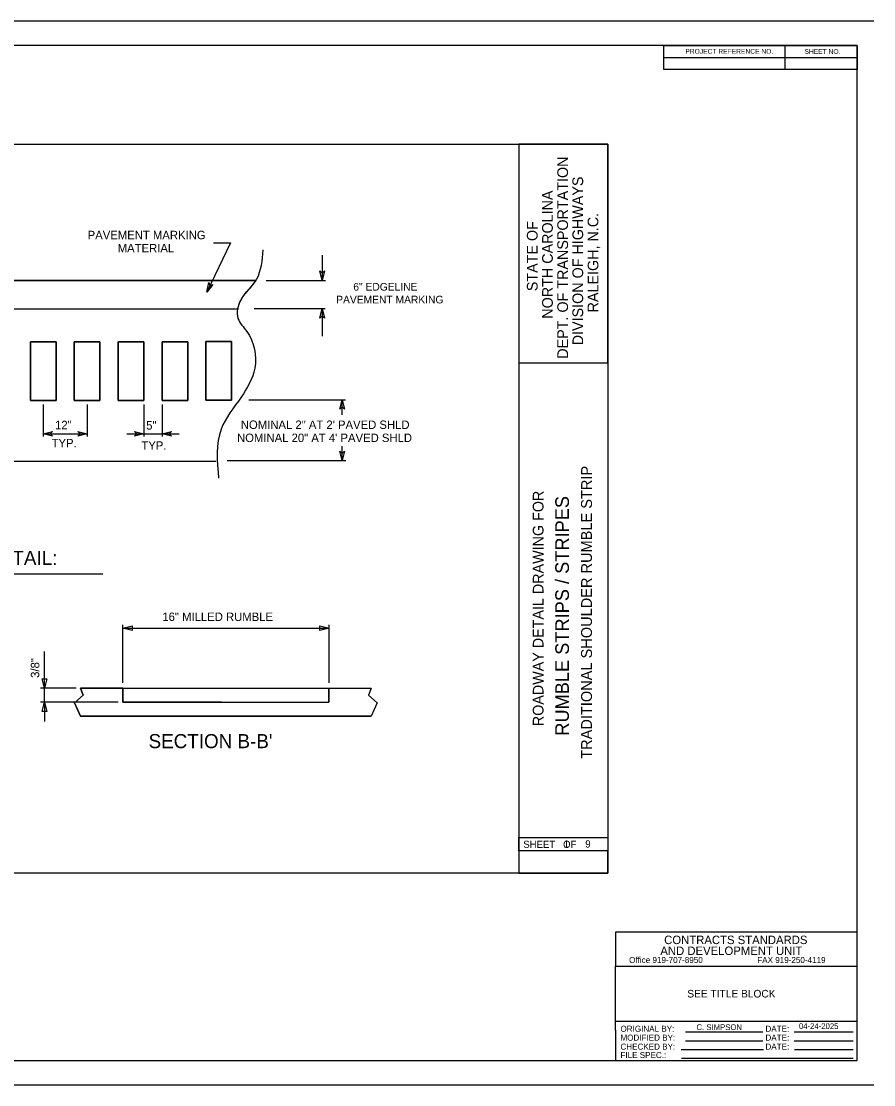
# Model space of a CAD drawing. Extents: x 1994737 to 2001433, y 527447 to 529360.
# Drawn here: x 1997988 to 1999041, y 527799 to 529114 of the extents above; entities that cross this region are included whole.
import ezdxf

# ---------------------------------------------------------------- set-up
doc = ezdxf.new("R2010")
doc.units = 0
for name, color, linetype in [('Default', 7, 'Continuous'), ('GSBWFILL', 7, 'Continuous'), ('Old_Level_1', 7, 'Continuous'), ('Old_Level_40', 7, 'Continuous'), ('Old_Level_60', 7, 'Continuous'), ('Prop Mkg Solid Yel Skip LT', 7, 'Continuous'), ('Prop Sign E Yield Sign Ahead CELL', 7, 'Continuous'), ('Prop Support Two', 7, 'Continuous')]:
    doc.layers.add(name, color=color, linetype=linetype)

# ---------------------------------------------------------------- blocks, each defined once
blk = doc.blocks.new('TERM2')
at = {"layer": 'Default'}
for p, q in [((-6.25, 1.563), (0, 0)), ((-4.687, 0), (-6.25, 1.563)), ((0, 0), (-6.25, -1.563)), ((-6.25, -1.563), (-4.687, 0))]:
    blk.add_line(p, q, dxfattribs=at)
blk = doc.blocks.new('TERM')
at = {"layer": 'Default'}
blk.add_lwpolyline([(-6.25, 1.563), (0, 0), (-6.25, -1.563)], close=True, dxfattribs=at)

msp = doc.modelspace()

# ---------------------------------------------------------------- linework, layer by layer
at = {"layer": 'Default'}
for p, q in [((1998246.1, 528840.3), (1998216.8, 528779.3)), ((1998225.3, 528840.3), (1998246.1, 528840.3)), ((1998359.5, 528824.8), (1998359.5, 528793.8)), ((1998290.3, 528793.8), (1998363.5, 528793.8)), ((1997470.2, 528793.5), (1998277.6, 528793.5)), ((1998277.3, 528793.5), (1997471.1, 528793.5)), ((1997492.7, 528758.5), (1998255.9, 528758.5)), ((1997493.1, 528758.5), (1998255.2, 528758.5)), ((1998275.4, 528758.9), (1998363.3, 528758.9)), ((1998359.5, 528758.8), (1998359.5, 528724.6)), ((1998014.6, 528640.4), (1998014.6, 528600.7)), ((1998068.9, 528640.4), (1998068.9, 528600.7)), ((1998138.9, 528640.4), (1998138.9, 528600.7)), ((1998161.5, 528640.4), (1998161.5, 528600.7)), ((1998268.7, 528646), (1998388.3, 528646)), ((1998384.2, 528627.6), (1998384.2, 528646)), ((1998014.4, 528604.1), (1998068.9, 528604.1)), ((1998118.1, 528604.1), (1998182.8, 528604.1)), ((1998384.2, 528571.2), (1998384.2, 528588.7)), ((1997520.3, 528570.4), (1998228.2, 528570.4)), ((1998242, 528571.2), (1998388.7, 528571.2)), ((1997826.2, 528431.2), (1998088.3, 528431.2)), ((1998113, 528296.3), (1998113, 528367.9)), ((1998113, 528364), (1998368, 528364)), ((1998368, 528296.3), (1998368, 528367.9)), ((1998016.4, 528289.8), (1998016.4, 528335.2)), ((1998055.5, 528289.8), (1998011.3, 528289.8)), ((1998016.4, 528272.4), (1998016.4, 528289.8)), ((1998060.6, 528289.8), (1998063.9, 528280.9)), ((1998060.6, 528289.8), (1998063.9, 528280.9)), ((1998113, 528289.8), (1998060.6, 528289.8)), ((1998060.6, 528289.8), (1998060.6, 528289.8)), ((1998060.6, 528289.8), (1998063.9, 528280.9)), ((1998063.9, 528280.9), (1998060.6, 528289.8)), ((1998060.6, 528289.8), (1998113, 528289.8)), ((1998113, 528289.8), (1998113, 528272.4)), ((1998113, 528272.4), (1998113, 528289.8)), ((1998113, 528289.8), (1998246.2, 528289.8)), ((1998246.2, 528289.8), (1998420.1, 528289.8)), ((1998367.8, 528289.8), (1998367.8, 528272.4)), ((1998367.8, 528289.8), (1998420.1, 528289.8)), ((1998367.8, 528288.1), (1998367.8, 528289.8)), ((1998367.8, 528272.4), (1998367.8, 528288.1)), ((1998420.1, 528289.8), (1998416.8, 528280.9)), ((1998420.1, 528289.8), (1998416.8, 528280.9)), ((1998107.1, 528272.4), (1998011.3, 528272.4)), ((1998016.4, 528272.4), (1998016.4, 528248.3)), ((1998063.9, 528280.9), (1998053.2, 528271.6)), ((1998063.9, 528280.9), (1998053.2, 528271.6)), ((1998053.2, 528271.6), (1998060.6, 528255)), ((1998053.2, 528271.6), (1998060.6, 528255)), ((1998113, 528272.4), (1998235.1, 528272.4)), ((1998235.1, 528272.4), (1998113, 528272.4)), ((1998235.1, 528272.4), (1998367.8, 528272.4)), ((1998235.1, 528272.4), (1998367.8, 528272.4)), ((1998416.8, 528280.9), (1998427.5, 528271.6)), ((1998416.8, 528280.9), (1998427.5, 528271.6)), ((1998427.5, 528271.6), (1998420.1, 528255)), ((1998427.5, 528271.6), (1998420.1, 528255)), ((1998060.6, 528255), (1998241, 528255)), ((1998060.6, 528255), (1998241, 528255)), ((1998241, 528255), (1998420.1, 528255)), ((1998420.1, 528255), (1998241, 528255))]:
    msp.add_line(p, q, dxfattribs=at)
for points in [[(1997294.9, 528962), (1998712.7, 528962), (1998712.7, 528061), (1997294.9, 528061)], [(1997998.9, 528717.7), (1998030.5, 528717.7), (1998030.5, 528645.3), (1997998.9, 528645.3)], [(1998053.1, 528717.6), (1998084.7, 528717.6), (1998084.7, 528645.2), (1998053.1, 528645.2)], [(1998107.4, 528717.6), (1998139, 528717.6), (1998139, 528645.2), (1998107.4, 528645.2)], [(1998161.7, 528717.6), (1998193.3, 528717.6), (1998193.3, 528645.2), (1998161.7, 528645.2)], [(1998215.8, 528718.1), (1998247.5, 528718.1), (1998247.5, 528645.7), (1998215.8, 528645.7)], [(1998367.8, 528289.8), (1998420.1, 528289.8), (1998416.8, 528280.9), (1998427.5, 528271.6), (1998420.1, 528255), (1998060.6, 528255), (1998053.2, 528271.6), (1998063.9, 528280.9), (1998060.6, 528289.8), (1998113, 528289.8), (1998113, 528272.4), (1998367.8, 528272.4)]]:
    msp.add_lwpolyline(points, close=True, dxfattribs=at)
for points in [[(1997998.9, 528645.3), (1998030.5, 528645.3), (1998030.5, 528717.7), (1997998.9, 528717.7), (1997998.9, 528645.3)], [(1998053.1, 528645.2), (1998084.7, 528645.2), (1998084.7, 528717.6), (1998053.1, 528717.6), (1998053.1, 528645.2)], [(1998107.4, 528645.2), (1998139, 528645.2), (1998139, 528717.6), (1998107.4, 528717.6), (1998107.4, 528645.2)], [(1998161.7, 528645.2), (1998193.3, 528645.2), (1998193.3, 528717.6), (1998161.7, 528717.6), (1998161.7, 528645.2)], [(1998215.8, 528645.7), (1998247.5, 528645.7), (1998247.5, 528718.1), (1998215.8, 528718.1), (1998215.8, 528645.7)]]:
    msp.add_lwpolyline(points, dxfattribs=at)
for points in [[(1998286.1, 528831.6), (1998278.1, 528795.1), (1998259.3, 528770.3), (1998255.4, 528746.6), (1998266.2, 528730.7), (1998276.1, 528685.1), (1998259.3, 528649.5), (1998234.6, 528609.9), (1998231.4, 528549.3)], [(1998255.2, 528758.5), (1998259.3, 528770.3), (1998261.2, 528773.5), (1998263.3, 528776.4), (1998268.2, 528781.9), (1998273.1, 528787.4), (1998275.4, 528790.4), (1998277.3, 528793.5)]]:
    msp.add_spline(points, degree=3, dxfattribs=at)
at = {"layer": 'GSBWFILL'}
for p, q in [((1999041.1, 529114.1), (1997028.6, 529114.1)), ((1997028.6, 527799.4), (1999041.1, 527799.4))]:
    msp.add_line(p, q, dxfattribs=at)
at = {"layer": 'Old_Level_40'}
for p, q in [((1998931.2, 529084.1), (1998931.2, 529054.3)), ((1998781.7, 529069.2), (1999020.8, 529069.2))]:
    msp.add_line(p, q, dxfattribs=at)
msp.add_lwpolyline([(1998781.7, 529084.2), (1999020.8, 529084.2), (1999020.8, 529054.3), (1998781.7, 529054.3)], close=True, dxfattribs=at)
at = {"layer": 'Old_Level_60'}
for p, q in [((1999020.8, 527988), (1998722, 527988)), ((1998722, 527988), (1998722, 527946.1)), ((1999020.8, 527829.3), (1999020.8, 527988)), ((1998722, 527866.7), (1998722, 527946.1)), ((1998722, 527946.1), (1999020.8, 527946.1)), ((1999020.8, 527877.7), (1998722, 527877.7)), ((1998722, 527866.7), (1998722, 527829.3)), ((1998808.4, 527864.9), (1998904.2, 527864.9)), ((1998942.9, 527864.9), (1999015.9, 527864.9)), ((1998808.4, 527853.8), (1998904.2, 527853.8)), ((1998942.9, 527853.8), (1999015.9, 527853.8)), ((1998803.1, 527842.8), (1998904.7, 527842.8)), ((1998943.3, 527842.8), (1999015.9, 527842.8)), ((1998722, 527829.3), (1999020.8, 527829.3)), ((1998803.5, 527832.3), (1999015.9, 527832.3))]:
    msp.add_line(p, q, dxfattribs=at)
msp.add_lwpolyline([(1998602.3, 528691.7), (1998712.7, 528691.7), (1998712.7, 528962), (1998602.3, 528962), (1998602.3, 528061), (1998712.7, 528061), (1998712.7, 528088.6), (1998602.3, 528088.6), (1998602.3, 528105.2), (1998712.7, 528105.2)], dxfattribs=at)
at = {"layer": 'Prop Sign E Yield Sign Ahead CELL'}
msp.add_lwpolyline([(1999020.8, 529084.2), (1997228.2, 529084.2), (1997228.2, 527829.3), (1999020.8, 527829.3)], close=True, dxfattribs=at)
at = {"layer": 'Prop Support Two'}
msp.add_line((1999041.1, 529114.1), (1999041.1, 529114.1), dxfattribs=at)

# ---------------------------------------------------------------- block references
at = {"layer": 'Default'}
for name, p, xscale, yscale, rotation in [('TERM2', (1998359.5, 528793.8), 1.8556685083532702, 1.8556685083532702, -89.99999999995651), ('TERM2', (1998216.8, 528779.3), 1.8556685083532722, 1.8556685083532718, -115.63251036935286), ('TERM2', (1998359.5, 528758.8), 1.8556685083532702, 1.8556685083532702, 90.00000000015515), ('TERM2', (1998384.2, 528646), 1.8556685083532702, 1.8556685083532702, 90.00000000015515), ('TERM2', (1998014.4, 528604.1), 1.8556685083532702, 1.8556685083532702, 179.99999999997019), ('TERM2', (1998068.9, 528604.1), 1.8556685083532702, 1.8556685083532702, -2.9817700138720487e-11), ('TERM2', (1998139.1, 528604.1), 1.8556685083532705, 1.8556685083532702, -0.009516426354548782), ('TERM2', (1998161.6, 528604.1), 1.855668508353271, 1.8556685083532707, -179.75274341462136), ('TERM2', (1998384.2, 528571.2), 1.8556685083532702, 1.8556685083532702, -89.99999999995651), ('TERM', (1998113, 528364), 1.8556685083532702, 1.8556685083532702, 179.9999999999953), ('TERM', (1998368, 528364), 1.8556685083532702, 1.8556685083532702, -4.686499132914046e-12), ('TERM', (1998016.4, 528289.8), 1.8556685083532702, 1.8556685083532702, -90.0000000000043), ('TERM', (1998016.4, 528272.4), 1.8556685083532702, 1.8556685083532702, 89.99999999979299)]:
    msp.add_blockref(name, p, dxfattribs=dict(at, xscale=xscale, yscale=yscale, rotation=rotation))

# ---------------------------------------------------------------- texts
for s, height, rotation, p in [('PAVEMENT MARKING', 10.438, 360, (1998069.6, 528844.6)), ('MATERIAL', 10.44, 360, (1998106.7, 528828.4)), ('6" EDGELINE', 9.489, 360, (1998397.9, 528781.1)), ('PAVEMENT MARKING', 9.489, 360, (1998376.8, 528765.3)), ('12"', 10.44, 360, (1998029.3, 528609.8)), ('5"', 10.44, 360, (1998141.9, 528609.3)), ('NOMINAL 2" AT 2\' PAVED SHLD', 10.438, 360, (1998258.9, 528610.1)), ('TYP.', 10.44, 360, (1998025, 528587.4)), ('NOMINAL 20" AT 4\' PAVED SHLD', 10.438, 360, (1998254.2, 528593.9)), ('TYP.', 10.44, 360, (1998136, 528584.4)), ('MILLING DETAIL:', 17.397, 0, (1997844.7, 528442)), ('16" MILLED RUMBLE', 10.438, 0, (1998161.9, 528372.7)), ('3/8"', 10.44, 90.0002, (1998009.8, 528302.4)), ("SECTION B-B'", 17.397, 0, (1998144.9, 528215.5))]:
    msp.add_text(s, height=height, rotation=rotation, dxfattribs=at).set_placement(p)
for s, p in [('C. SIMPSON', (1998822.1, 527867)), ('04-24-2025', (1998948.7, 527868.3))]:
    msp.add_text(s, height=7.14, dxfattribs=at).set_placement(p)
at = {"layer": 'Old_Level_1'}
for s, height, p in [('TRADITIONAL SHOULDER RUMBLE STRIP', 13.461, (1998692.9, 528202.4)), ('RUMBLE STRIPS / STRIPES', 16.826, (1998664.4, 528230.9))]:
    msp.add_text(s, height=height, rotation=90, dxfattribs=at).set_placement(p)
msp.add_text('1      9', height=8.97, dxfattribs=at).set_placement((1998657.9, 528092.6))
at = {"layer": 'Old_Level_60'}
for s, height, rotation, p in [('DEPT. OF TRANSPORTATION', 13.245, 90, (1998663.3, 528696.9)), ('DEPT. OF TRANSPORTATION', 13.245, 90, (1998663.3, 528696.9)), ('DIVISION OF HIGHWAYS', 13.245, 90, (1998682, 528713.5)), ('DIVISION OF HIGHWAYS', 13.245, 90, (1998682, 528713.5)), ('NORTH CAROLINA', 13.245, 90, (1998644.5, 528746.4)), ('NORTH CAROLINA', 13.245, 90, (1998644.5, 528746.4)), ('RALEIGH, N.C.', 13.245, 90, (1998700.8, 528754.2)), ('RALEIGH, N.C.', 13.245, 90, (1998700.8, 528754.2)), ('STATE OF', 13.24, 90, (1998625.7, 528780.4)), ('STATE OF', 13.24, 90, (1998625.7, 528780.4)), ('ROADWAY DETAIL DRAWING FOR', 13.236, 90, (1998633, 528242.7)), ('SEE TITLE BLOCK', 9.406, 0.0008, (1998810.7, 527907.3))]:
    msp.add_text(s, height=height, rotation=rotation, dxfattribs=at).set_placement(p)
for s, height, p in [('SHEET   OF', 8.83, (1998608, 528092.2)), ('SHEET   OF', 8.83, (1998608, 528092.2)), ('CONTRACTS STANDARDS', 10.457, (1998782.1, 527973.3)), ('AND DEVELOPMENT UNIT', 10.457, (1998777.4, 527959.8)), ('Office 919-707-8950', 7.469, (1998738.8, 527949.9)), ('FAX 919-250-4119', 7.469, (1998897.2, 527949.9)), ('ORIGINAL BY:', 7.469, (1998728.1, 527864.9)), ('MODIFIED BY:', 7.469, (1998728.1, 527853.9)), ('DATE:', 7.47, (1998907.3, 527864.9)), ('DATE:', 7.47, (1998907.3, 527853.9)), ('CHECKED BY:', 7.469, (1998728.1, 527842.8)), ('DATE:', 7.47, (1998907.3, 527842.8)), ('FILE SPEC.:', 7.469, (1998728.1, 527832.4))]:
    msp.add_text(s, height=height, dxfattribs=at).set_placement(p)
at = {"layer": 'Prop Mkg Solid Yel Skip LT'}
for s, height, p in [('PROJECT REFERENCE NO.', 5.976, (1998808.3, 529073.9)), ('SHEET NO.', 5.98, (1998955.5, 529073.7))]:
    msp.add_text(s, height=height, dxfattribs=at).set_placement(p)

doc.saveas('drawing.dxf')
